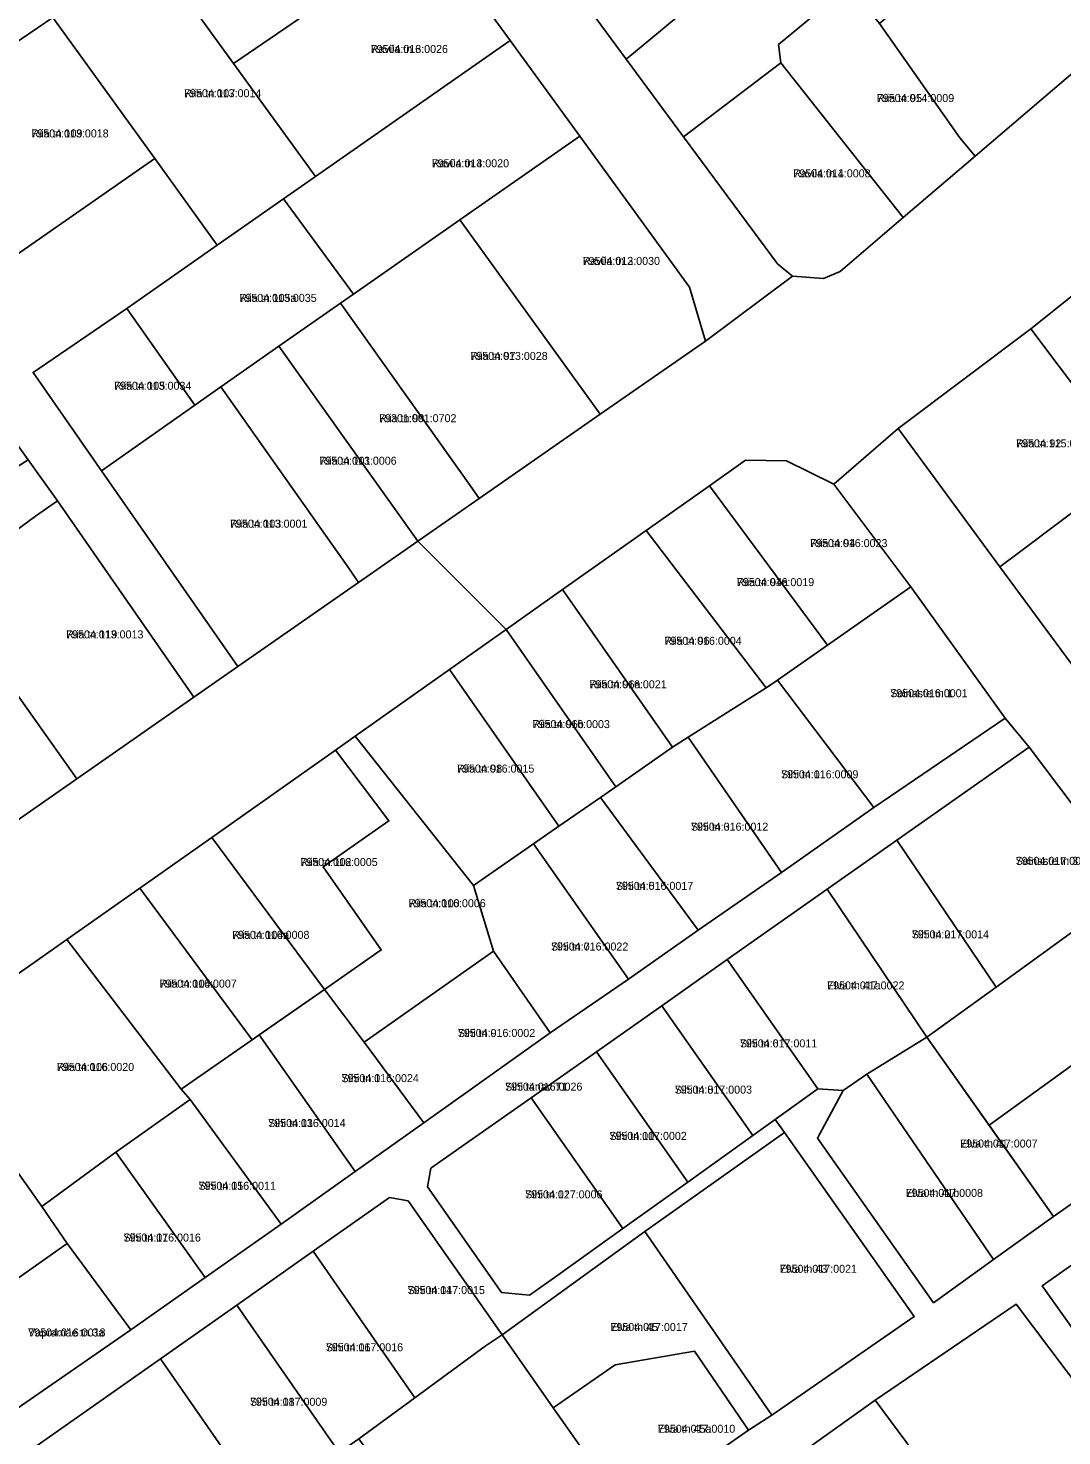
# Model space of a CAD drawing. Extents: x 643847 to 663718, y 6468443 to 6482775.
# Drawn here: x 657732.5 to 657926.4, y 6472259.5 to 6472523.3 of the extents above; entities that cross this region are included whole.
import ezdxf

# ---------------------------------------------------------------- set-up
doc = ezdxf.new("R2010")
doc.units = 0
for name, color, linetype in [('L_AADRESS', 7, 'Continuous'), ('PIIR', 7, 'Continuous'), ('TUNNUS', 7, 'Continuous')]:
    doc.layers.add(name, color=color, linetype=linetype)

msp = doc.modelspace()

# ---------------------------------------------------------------- linework, layer by layer
at = {"layer": 'PIIR'}
for points in [[(657873.04, 6472479.14), (657875.83, 6472476.86), (657859.5, 6472464.68), (657856.51, 6472474.77), (657835.95, 6472503.11), (657822.87, 6472521.04), (657807.77, 6472541.8), (657792.52, 6472562.77), (657772.39, 6472590.41), (657766.14, 6472598.47), (657745.85, 6472626.02), (657725.82, 6472653.21), (657710.38, 6472666.6), (657734.13, 6472682.54), (657738.75, 6472661.72), (657758.63, 6472634.67), (657778.9, 6472607.11), (657784.86, 6472598.74), (657805.14, 6472571.21), (657818.04, 6472553.13), (657831.47, 6472535.44), (657844.68, 6472517.51), (657855.38, 6472502.98)], [(657792.52, 6472562.77), (657807.77, 6472541.8), (657771.04, 6472516.68), (657755.68, 6472537.86), (657771.95, 6472548.92)], [(657719.72, 6472554.93), (657722.52, 6472550.79), (657738.86, 6472526.55), (657737.12, 6472525.31), (657722.37, 6472515.34), (657703.12, 6472543.7)], [(657831.47, 6472535.44), (657835.5, 6472538.41), (657855.23, 6472552.94), (657857.4, 6472550.27), (657867.29, 6472536.3), (657848.53, 6472520.71), (657844.68, 6472517.51)], [(657892.19, 6472524.23), (657910.71, 6472539.92), (657927.25, 6472553.66), (657946.8, 6472530.68), (657910.09, 6472499.35), (657907.24, 6472502.76)], [(657822.87, 6472521.04), (657786.37, 6472495.56), (657771.04, 6472516.68), (657807.77, 6472541.8)], [(657844.68, 6472517.51), (657848.53, 6472520.71), (657867.29, 6472536.3), (657876.29, 6472543.83), (657886.45, 6472531.25), (657873.23, 6472520.25), (657873.67, 6472516.82), (657855.38, 6472502.98)], [(657771.04, 6472516.68), (657786.37, 6472495.56), (657780.41, 6472491.36), (657767.97, 6472482.69), (657756.24, 6472498.9), (657737.12, 6472525.31), (657738.86, 6472526.55), (657755.68, 6472537.86)], [(657896.6, 6472487.85), (657873.67, 6472516.82), (657873.23, 6472520.25), (657886.45, 6472531.25), (657892.19, 6472524.23), (657907.24, 6472502.76), (657910.09, 6472499.35)], [(657729.71, 6472480.39), (657709.81, 6472506.85), (657722.37, 6472515.34), (657737.12, 6472525.31), (657756.24, 6472498.9)], [(657813.48, 6472487.43), (657793.51, 6472473.49), (657780.41, 6472491.36), (657786.37, 6472495.56), (657822.87, 6472521.04), (657835.95, 6472503.11)], [(657855.38, 6472502.98), (657873.67, 6472516.82), (657896.6, 6472487.85), (657884.78, 6472477.72), (657881.65, 6472476.44), (657875.83, 6472476.86), (657873.04, 6472479.14)], [(657839.79, 6472450.97), (657838.04, 6472453.4), (657813.48, 6472487.43), (657835.95, 6472503.11), (657856.51, 6472474.77), (657859.5, 6472464.68)], [(657771.81, 6472403.7), (657763.57, 6472397.95), (657738.01, 6472434.76), (657732.48, 6472442.44), (657724.75, 6472453.17), (657694.58, 6472431.73), (657688.98, 6472427.57), (657676.82, 6472443.49), (657703.22, 6472461.9), (657729.71, 6472480.39), (657756.24, 6472498.9), (657767.96, 6472482.69), (657751.03, 6472470.78), (657733.43, 6472458.82), (657746.26, 6472440.34)], [(657751.03, 6472470.78), (657767.96, 6472482.69), (657780.41, 6472491.36), (657793.51, 6472473.49), (657791.07, 6472471.78), (657779.53, 6472463.73), (657768.63, 6472456.13), (657763.78, 6472452.69)], [(657817.11, 6472435.2), (657815.38, 6472437.64), (657791.07, 6472471.78), (657793.51, 6472473.49), (657813.48, 6472487.43), (657838.04, 6472453.4), (657839.79, 6472450.97)], [(657946.06, 6472487.35), (657962.55, 6472465.09), (657936.28, 6472446.05), (657920.56, 6472467)], [(657733.43, 6472458.82), (657751.03, 6472470.78), (657763.78, 6472452.69), (657746.26, 6472440.34)], [(657817.11, 6472435.2), (657805.58, 6472427.18), (657779.53, 6472463.73), (657791.07, 6472471.78), (657815.38, 6472437.64)], [(657920.56, 6472467), (657936.28, 6472446.05), (657939.88, 6472441.24), (657918.68, 6472425.34), (657914.74, 6472422.38), (657895.64, 6472448.31)], [(657805.58, 6472427.18), (657794.48, 6472419.46), (657792.75, 6472421.91), (657768.63, 6472456.13), (657779.53, 6472463.73)], [(657794.48, 6472419.46), (657771.81, 6472403.7), (657746.26, 6472440.34), (657763.78, 6472452.69), (657768.63, 6472456.13), (657792.75, 6472421.91)], [(657898.03, 6472418.61), (657883.59, 6472437.84), (657895.64, 6472448.31), (657914.74, 6472422.38), (657928.08, 6472404.27), (657941.51, 6472386.22), (657954.95, 6472368.16), (657971.33, 6472346.15), (657977.32, 6472338.42), (657993.44, 6472316.73), (658004.21, 6472302.3), (658019.23, 6472282.55), (658029.94, 6472268.09), (658042.89, 6472250.88), (658028.98, 6472242.9), (658014.09, 6472262.87), (658003.39, 6472277.2), (657992.33, 6472292.03), (657970.47, 6472321.31), (657964.96, 6472328.73), (657952.1, 6472346.06), (657939.98, 6472362.39), (657920.22, 6472388.56), (657915.74, 6472393.98)], [(657738.01, 6472434.76), (657733.89, 6472431.88), (657723.57, 6472424.32), (657715.67, 6472419.17), (657693.39, 6472403.63), (657690.92, 6472401.91), (657683.72, 6472411.57), (657719.65, 6472437.14), (657721.08, 6472435.19), (657732.48, 6472442.44)], [(657867.06, 6472442.36), (657874.75, 6472442.27), (657883.59, 6472437.84), (657898.03, 6472418.61), (657882.39, 6472407.69), (657860.27, 6472437.56)], [(657914.74, 6472422.38), (657918.68, 6472425.34), (657939.88, 6472441.24), (657947.29, 6472431.49), (657953.39, 6472423.25), (657932.18, 6472407.35), (657928.08, 6472404.27)], [(657860.27, 6472437.56), (657882.39, 6472407.69), (657873.02, 6472401.16), (657870.91, 6472399.67), (657848.42, 6472429.2)], [(657741.62, 6472382.66), (657715.67, 6472419.17), (657723.57, 6472424.32), (657733.89, 6472431.88), (657738.01, 6472434.76), (657763.57, 6472397.95)], [(657848.42, 6472429.2), (657870.91, 6472399.67), (657856.3, 6472390.44), (657853.36, 6472388.59), (657832.74, 6472418.14)], [(657719.65, 6472367.35), (657717.85, 6472369.83), (657693.39, 6472403.63), (657715.67, 6472419.17), (657741.62, 6472382.66)], [(657832.74, 6472418.14), (657853.36, 6472388.59), (657842.69, 6472381.17), (657822.13, 6472410.62)], [(657915.74, 6472393.98), (657891.11, 6472377.27), (657873.02, 6472401.16), (657882.39, 6472407.69), (657898.03, 6472418.61)], [(657822.13, 6472410.62), (657842.69, 6472381.17), (657839.82, 6472379.16), (657832.03, 6472373.74), (657811.51, 6472403.11)], [(657811.51, 6472403.11), (657832.03, 6472373.74), (657816.03, 6472362.62), (657793.82, 6472390.63)], [(657873.79, 6472365.1), (657856.3, 6472390.44), (657870.91, 6472399.67), (657873.02, 6472401.16), (657891.11, 6472377.27)], [(657793.82, 6472390.63), (657816.03, 6472362.62), (657819.78, 6472350.36), (657795.51, 6472333.3), (657788.05, 6472343.16), (657798.72, 6472350.58), (657787.86, 6472366.17), (657800.17, 6472374.74), (657790.15, 6472388.03)], [(657858.17, 6472354.28), (657839.82, 6472379.16), (657842.69, 6472381.17), (657853.36, 6472388.59), (657856.3, 6472390.44), (657873.79, 6472365.1)], [(657920.22, 6472388.56), (657939.98, 6472362.39), (657914.02, 6472343.6), (657895.41, 6472371.13)], [(657790.15, 6472388.03), (657800.17, 6472374.74), (657787.86, 6472366.17), (657798.72, 6472350.58), (657788.05, 6472343.16), (657766.93, 6472371.66)], [(657845.08, 6472345.09), (657827.28, 6472370.44), (657832.03, 6472373.74), (657839.82, 6472379.16), (657858.17, 6472354.28)], [(657766.93, 6472371.66), (657788.05, 6472343.16), (657774.51, 6472333.73), (657753.46, 6472362.16)], [(657830.4, 6472335.04), (657819.78, 6472350.36), (657816.03, 6472362.62), (657827.28, 6472370.44), (657845.08, 6472345.09)], [(657895.41, 6472371.13), (657914.02, 6472343.6), (657901.06, 6472334.22), (657882.37, 6472361.95)], [(657753.46, 6472362.16), (657774.51, 6472333.73), (657761.21, 6472324.47), (657739.73, 6472352.52)], [(657882.37, 6472361.95), (657901.06, 6472334.22), (657889.78, 6472327.3), (657885.35, 6472324.21), (657880.62, 6472324.52), (657863.61, 6472348.75)], [(657952.1, 6472346.06), (657932.61, 6472332.07), (657912.7, 6472317.76), (657901.06, 6472334.22), (657914.02, 6472343.6), (657939.98, 6472362.39)], [(657739.73, 6472352.52), (657761.21, 6472324.47), (657762.86, 6472322.52), (657748.96, 6472312.67), (657735.07, 6472302.5), (657723.46, 6472318.83), (657712.91, 6472333.66)], [(657806.71, 6472318.16), (657795.51, 6472333.3), (657819.78, 6472350.36), (657830.4, 6472335.04)], [(657863.61, 6472348.75), (657880.62, 6472324.52), (657868.42, 6472315.79), (657851.35, 6472340.12)], [(657806.71, 6472318.16), (657793.84, 6472309.02), (657775.83, 6472334.65), (657788.05, 6472343.16), (657795.51, 6472333.3)], [(657851.35, 6472340.12), (657868.42, 6472315.79), (657856.22, 6472307.07), (657839.08, 6472331.5)], [(657779.97, 6472299.18), (657762.86, 6472322.52), (657761.21, 6472324.47), (657774.51, 6472333.73), (657775.83, 6472334.65), (657793.84, 6472309.02)], [(657913.56, 6472292.53), (657889.78, 6472327.3), (657901.06, 6472334.22), (657924.82, 6472300.62)], [(657839.08, 6472331.5), (657856.22, 6472307.07), (657844.02, 6472298.35), (657826.81, 6472322.87)], [(657924.82, 6472300.62), (657912.7, 6472317.76), (657932.61, 6472332.07), (657944.86, 6472314.65)], [(657902.31, 6472284.45), (657880.56, 6472315.32), (657885.35, 6472324.21), (657889.78, 6472327.3), (657913.56, 6472292.53)], [(657765.71, 6472289.17), (657748.96, 6472312.67), (657762.86, 6472322.52), (657779.97, 6472299.18)], [(657814.55, 6472314.24), (657826.81, 6472322.87), (657844.02, 6472298.35), (657831.82, 6472289.62), (657826.53, 6472285.84), (657821.25, 6472286.38), (657807.39, 6472306.16), (657808, 6472309.65)], [(657696.17, 6472299.95), (657723.46, 6472318.83), (657735.07, 6472302.5), (657739.8, 6472295.58), (657713.03, 6472276.71)], [(657871.95, 6472263.38), (657848.18, 6472297.77), (657874.34, 6472316.35), (657898.69, 6472281.85)], [(657751.74, 6472279.35), (657739.8, 6472295.58), (657735.07, 6472302.5), (657748.96, 6472312.67), (657765.71, 6472289.17)], [(657800.27, 6472304.16), (657803.75, 6472303.56), (657821.37, 6472278.45), (657818.24, 6472276.32), (657805, 6472266.64), (657785.96, 6472294.09)], [(657943.83, 6472302.52), (657963.86, 6472276.31), (657941.58, 6472260.98), (657922.66, 6472287.6)], [(657867.58, 6472260.54), (657857.49, 6472275.35), (657842.58, 6472272.81), (657830.98, 6472264.78), (657821.37, 6472278.45), (657848.18, 6472297.77), (657871.95, 6472263.38)], [(657713.03, 6472276.71), (657739.8, 6472295.58), (657751.74, 6472279.35), (657724.68, 6472260.69)], [(657785.96, 6472294.09), (657805, 6472266.64), (657794.51, 6472258.95), (657790.86, 6472256.37), (657771.65, 6472284.02)], [(657771.65, 6472284.02), (657790.86, 6472256.37), (657776.49, 6472246.35), (657757.34, 6472273.95)], [(657917.78, 6472284.21), (657945.7, 6472247.12), (657927.49, 6472232.86), (657920.45, 6472227), (657909.86, 6472241.24), (657891.33, 6472266.16)], [(657818.24, 6472226.11), (657794.51, 6472258.95), (657805, 6472266.64), (657818.24, 6472276.32), (657821.37, 6472278.45), (657830.98, 6472264.78), (657845.05, 6472244.8)], [(657845.05, 6472244.8), (657830.98, 6472264.78), (657842.58, 6472272.81), (657857.49, 6472275.35), (657867.58, 6472260.54)], [(657747.96, 6472229.69), (657729.57, 6472254.42), (657757.34, 6472273.95), (657776.49, 6472246.35), (657770.93, 6472242.4), (657749.63, 6472227.26)], [(657909.86, 6472241.24), (657888.57, 6472225.79), (657871.8, 6472248.9), (657872.07, 6472252.45), (657891.33, 6472266.16)]]:
    msp.add_lwpolyline(points, close=True, dxfattribs=at)
for points in [[(657946.06, 6472487.35), (657920.56, 6472467), (657895.64, 6472448.31), (657883.59, 6472437.84), (657874.75, 6472442.27), (657867.06, 6472442.36), (657860.27, 6472437.56), (657848.42, 6472429.2), (657832.74, 6472418.14), (657822.13, 6472410.62), (657805.58, 6472427.18), (657817.11, 6472435.2), (657839.79, 6472450.97), (657859.5, 6472464.68), (657875.83, 6472476.86), (657881.65, 6472476.44), (657884.78, 6472477.72), (657896.6, 6472487.85), (657910.09, 6472499.35), (657946.8, 6472530.68)], [(657719.65, 6472367.35), (657741.62, 6472382.66), (657763.57, 6472397.95), (657771.81, 6472403.7), (657794.48, 6472419.46), (657805.58, 6472427.18), (657822.13, 6472410.62), (657811.51, 6472403.11), (657793.82, 6472390.63), (657790.15, 6472388.03), (657766.93, 6472371.66), (657753.46, 6472362.16), (657739.73, 6472352.52), (657712.91, 6472333.66)], [(657724.68, 6472260.69), (657751.74, 6472279.35), (657765.71, 6472289.17), (657779.97, 6472299.18), (657793.84, 6472309.02), (657806.71, 6472318.16), (657830.4, 6472335.04), (657845.08, 6472345.09), (657858.17, 6472354.28), (657873.79, 6472365.1), (657891.11, 6472377.27), (657915.74, 6472393.98), (657920.22, 6472388.56), (657895.41, 6472371.13), (657882.37, 6472361.95), (657863.61, 6472348.75), (657851.35, 6472340.12), (657839.08, 6472331.5), (657826.81, 6472322.87), (657814.55, 6472314.24), (657808, 6472309.65), (657807.39, 6472306.16), (657821.25, 6472286.38), (657826.53, 6472285.84), (657831.82, 6472289.62), (657844.02, 6472298.35), (657856.22, 6472307.07), (657868.42, 6472315.79), (657872.61, 6472318.77), (657874.34, 6472316.35), (657848.18, 6472297.77), (657821.37, 6472278.45), (657803.75, 6472303.56), (657800.27, 6472304.16), (657785.96, 6472294.09), (657771.65, 6472284.02), (657757.34, 6472273.95), (657729.57, 6472254.42)], [(657845.05, 6472244.8), (657867.58, 6472260.54), (657871.95, 6472263.38), (657898.69, 6472281.85), (657874.34, 6472316.35), (657872.61, 6472318.77), (657880.62, 6472324.52), (657885.35, 6472324.21), (657880.56, 6472315.32), (657902.31, 6472284.45), (657913.56, 6472292.53), (657924.82, 6472300.62), (657944.86, 6472314.65)], [(657943.83, 6472302.52), (657922.66, 6472287.6), (657941.58, 6472260.98)], [(657945.7, 6472247.12), (657917.78, 6472284.21), (657891.33, 6472266.16), (657872.07, 6472252.45)]]:
    msp.add_lwpolyline(points, dxfattribs=at)

# ---------------------------------------------------------------- texts
at = {"layer": 'L_AADRESS'}
for s, p in [('Ravila tn 6', (657796.73, 6472518.68)), ('Riia tn 107', (657761.74, 6472510.39)), ('Riia tn 95', (657891.66, 6472509.48)), ('Riia tn 109', (657733.1, 6472502.85)), ('Ravila tn 4', (657808.19, 6472497.26)), ('Ravila tn 1', (657875.99, 6472495.37)), ('Ravila tn 2', (657836.49, 6472478.96)), ('Riia tn 105a', (657772.11, 6472472.03)), ('Riia tn 97', (657815.43, 6472461.15)), ('Riia tn 105', (657748.61, 6472455.56)), ('Riia tn 99', (657798.32, 6472449.48)), ('Riia tn 92', (657917.76, 6472444.77)), ('Riia tn 101', (657787.11, 6472441.51)), ('Riia tn 103', (657770.37, 6472429.71)), ('Riia tn 94', (657879.15, 6472426.07)), ('Riia tn 94a', (657865.41, 6472418.76)), ('Riia tn 119', (657739.62, 6472408.96)), ('Riia tn 96', (657851.82, 6472407.76)), ('Riia tn 96a', (657837.75, 6472399.61)), ('Soinaste tn 1', (657894.18, 6472397.94)), ('Riia tn 96b', (657827.1, 6472392.15)), ('Riia tn 98', (657812.93, 6472383.81)), ('Sihi tn 1', (657873.7, 6472382.74)), ('Sihi tn 3', (657856.8, 6472372.92)), ('Riia tn 102', (657783.55, 6472366.3)), ('Soinaste tn 3', (657917.69, 6472366.52)), ('Sihi tn 5', (657842.73, 6472361.83)), ('Riia tn 100', (657803.82, 6472358.58)), ('Riia tn 104a', (657770.75, 6472352.65)), ('Sihi tn 2', (657898.2, 6472352.74)), ('Sihi tn 7', (657830.55, 6472350.46)), ('Riia tn 104', (657757.12, 6472343.51)), ('Elva tn 41a', (657882.34, 6472343.17)), ('Sihi tn 9', (657813.09, 6472334.26)), ('Sihi tn 6', (657865.98, 6472332.31)), ('Riia tn 106', (657737.88, 6472327.89)), ('Sihi tn 11', (657791.27, 6472325.79)), ('Sihi tänav T1', (657821.94, 6472324.2)), ('Sihi tn 8', (657853.75, 6472323.64)), ('Sihi tn 13', (657777.53, 6472317.38)), ('Sihi tn 10', (657841.52, 6472314.97)), ('Elva tn 41', (657907.3, 6472313.54)), ('Sihi tn 15', (657764.46, 6472305.62)), ('Sihi tn 12', (657825.71, 6472304.01)), ('Elva tn 41b', (657897.06, 6472304.28)), ('Sihi tn 17', (657750.39, 6472295.92)), ('Elva tn 43', (657873.43, 6472290.06)), ('Sihi tn 14', (657803.66, 6472286.07)), ('Elva tn 45', (657841.7, 6472279.15)), ('Vapramäe tn 3a', (657732.51, 6472278.13)), ('Sihi tn 16', (657788.32, 6472275.35)), ('Sihi tn 18', (657774.1, 6472265.14)), ('Elva tn 45a', (657850.6, 6472260.08))]:
    msp.add_text(s, height=1.5, dxfattribs=at).set_placement(p)
at = {"layer": 'TUNNUS'}
for s, p in [('79504:013:0026', (657796.73, 6472518.68)), ('79504:013:0014', (657761.74, 6472510.39)), ('79504:014:0009', (657891.66, 6472509.48)), ('79504:013:0018', (657733.1, 6472502.85)), ('79504:013:0020', (657808.19, 6472497.26)), ('79504:014:0008', (657875.99, 6472495.37)), ('79504:013:0030', (657836.49, 6472478.96)), ('79504:013:0035', (657772.11, 6472472.03)), ('79504:013:0028', (657815.43, 6472461.15)), ('79504:013:0034', (657748.61, 6472455.56)), ('79301:001:0702', (657798.32, 6472449.48)), ('79504:115:0001', (657917.76, 6472444.77)), ('79504:013:0006', (657787.11, 6472441.51)), ('79504:013:0001', (657770.37, 6472429.71)), ('79504:016:0023', (657879.15, 6472426.07)), ('79504:016:0019', (657865.41, 6472418.76)), ('79504:013:0013', (657739.62, 6472408.96)), ('79504:016:0004', (657851.82, 6472407.76)), ('79504:016:0021', (657837.75, 6472399.61)), ('79504:016:0001', (657894.18, 6472397.94)), ('79504:016:0003', (657827.1, 6472392.15)), ('79504:016:0015', (657812.93, 6472383.81)), ('79504:016:0009', (657873.7, 6472382.74)), ('79504:016:0012', (657856.8, 6472372.92)), ('79504:016:0005', (657783.55, 6472366.3)), ('79504:017:0023', (657917.69, 6472366.52)), ('79504:016:0017', (657842.73, 6472361.83)), ('79504:016:0006', (657803.82, 6472358.58)), ('79504:016:0008', (657770.75, 6472352.65)), ('79504:017:0014', (657898.2, 6472352.74)), ('79504:016:0022', (657830.55, 6472350.46)), ('79504:016:0007', (657757.12, 6472343.51)), ('79504:017:0022', (657882.34, 6472343.17)), ('79504:016:0002', (657813.09, 6472334.26)), ('79504:017:0011', (657865.98, 6472332.31)), ('79504:016:0020', (657737.88, 6472327.89)), ('79504:016:0024', (657791.27, 6472325.79)), ('79504:016:0026', (657821.94, 6472324.2)), ('79504:017:0003', (657853.75, 6472323.64)), ('79504:016:0014', (657777.53, 6472317.38)), ('79504:017:0002', (657841.52, 6472314.97)), ('79504:017:0007', (657907.3, 6472313.54)), ('79504:016:0011', (657764.46, 6472305.62)), ('79504:017:0006', (657825.71, 6472304.01)), ('79504:017:0008', (657897.06, 6472304.28)), ('79504:016:0016', (657750.39, 6472295.92)), ('79504:017:0021', (657873.43, 6472290.06)), ('79504:017:0015', (657803.66, 6472286.07)), ('79504:017:0017', (657841.7, 6472279.15)), ('79504:016:0018', (657732.51, 6472278.13)), ('79504:017:0016', (657788.32, 6472275.35)), ('79504:017:0009', (657774.1, 6472265.14)), ('79504:017:0010', (657850.6, 6472260.08))]:
    msp.add_text(s, height=1.5, dxfattribs=at).set_placement(p)

doc.saveas('drawing.dxf')
